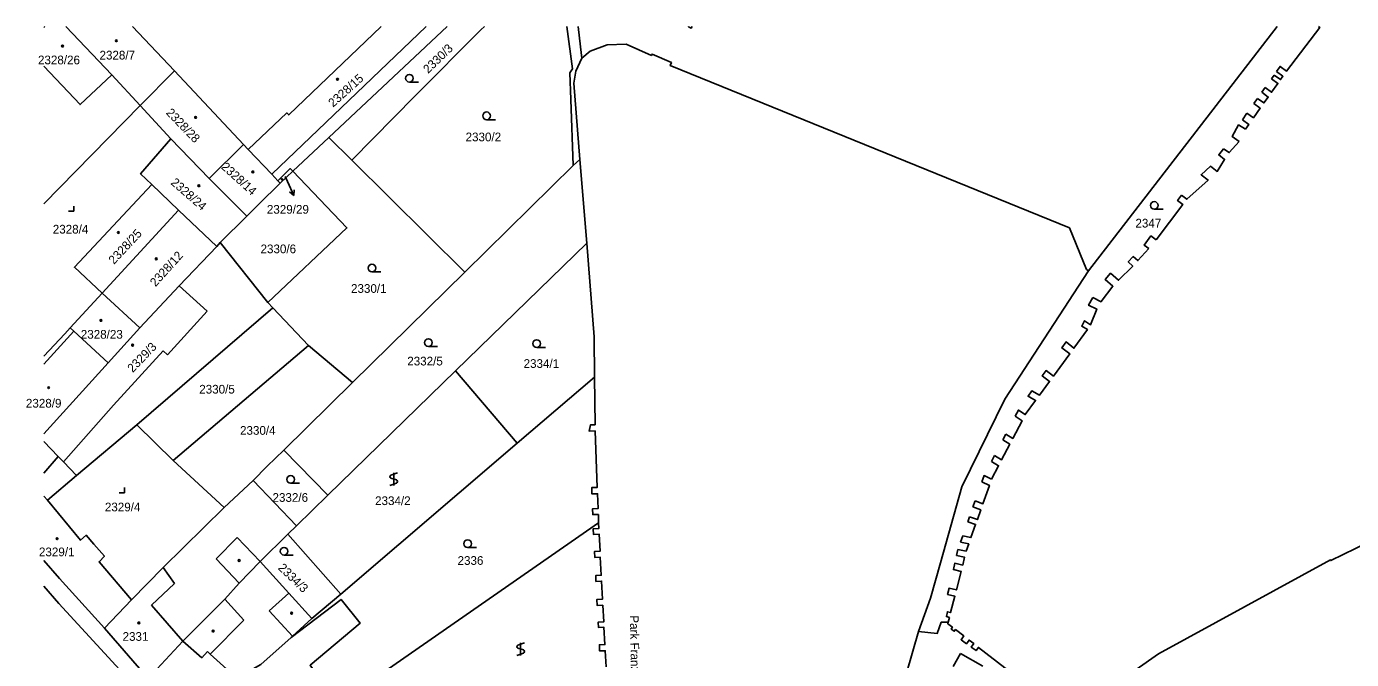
# Model space of a CAD drawing. Extents: x -600849 to -599899, y -1204328 to -1203436.
# Drawn here: x -600846.5 to -600587.3, y -1203561.9 to -1203438.2 of the extents above; entities that cross this region are included whole.
import ezdxf

# ---------------------------------------------------------------- set-up
doc = ezdxf.new("R2010")
doc.units = 0
for name, color, linetype in [('Vrstva 1', 7, 'Continuous'), ('Vrstva 2', 7, 'Continuous'), ('Vrstva 3', 7, 'Continuous'), ('Vrstva 4', 7, 'Continuous'), ('Vrstva 5', 7, 'Continuous'), ('Vrstva 7', 7, 'Continuous')]:
    doc.layers.add(name, color=color, linetype=linetype)

msp = doc.modelspace()

# ---------------------------------------------------------------- linework, layer by layer
at = {"layer": 'Vrstva 1'}
for p, q in [((-600843.16, -1203438.38), (-600842.94, -1203438.18)), ((-600838.82, -1203438.18), (-600829.8, -1203447.65)), ((-600825.76, -1203438.18), (-600817.54, -1203446.84)), ((-600787.39, -1203459.87), (-600764.25, -1203438.18)), ((-600756.95, -1203438.18), (-600757.64, -1203438.83)), ((-600738.62, -1203438.18), (-600738.16, -1203442.17)), ((-600638.77, -1203485.91), (-600601.89, -1203438.18)), ((-600738.16, -1203442.17), (-600737.91, -1203444.35)), ((-600737.91, -1203444.35), (-600739.05, -1203446.92)), ((-600829.8, -1203447.65), (-600824.28, -1203453.64)), ((-600824.28, -1203453.64), (-600817.54, -1203446.84)), ((-600817.54, -1203446.84), (-600804.07, -1203461.23)), ((-600739.05, -1203446.92), (-600739.48, -1203449.28)), ((-600602.47, -1203447.67), (-600602.99, -1203448.4)), ((-600739.48, -1203449.28), (-600738.28, -1203464.19)), ((-600604.21, -1203450.12), (-600604.85, -1203451.02)), ((-600605.72, -1203452.24), (-600606.44, -1203453.26)), ((-600818.26, -1203460.12), (-600824.28, -1203453.64)), ((-600607.78, -1203455.14), (-600608.68, -1203456.41)), ((-600810.81, -1203467.88), (-600818.26, -1203460.12)), ((-600794.44, -1203466.48), (-600787.39, -1203459.87)), ((-600782.9, -1203464.28), (-600787.39, -1203459.87)), ((-600804.07, -1203461.23), (-600810.81, -1203467.88)), ((-600804.07, -1203461.23), (-600803.13, -1203462.23)), ((-600798.54, -1203467.06), (-600803.13, -1203462.23)), ((-600760.8, -1203486.2), (-600782.9, -1203464.28)), ((-600760.8, -1203486.2), (-600739.59, -1203465.37)), ((-600739.59, -1203465.37), (-600738.28, -1203464.19)), ((-600738.28, -1203464.19), (-600736.94, -1203480.55)), ((-600803.43, -1203475.24), (-600810.81, -1203467.88)), ((-600798.54, -1203467.06), (-600797.34, -1203468.33)), ((-600797.34, -1203468.33), (-600796.88, -1203468.81)), ((-600796.88, -1203468.81), (-600794.44, -1203466.48)), ((-600822.02, -1203469.05), (-600816.81, -1203474.09)), ((-600816.81, -1203474.09), (-600831.7, -1203490.3)), ((-600816.81, -1203474.09), (-600809.32, -1203481.16)), ((-600808.61, -1203480.42), (-600803.43, -1203475.24)), ((-600809.32, -1203481.16), (-600808.61, -1203480.42)), ((-600799.3, -1203492.1), (-600808.61, -1203480.42)), ((-600736.94, -1203480.55), (-600762.57, -1203505.5)), ((-600782.77, -1203507.78), (-600760.8, -1203486.2)), ((-600638.77, -1203485.91), (-600639.18, -1203485.68)), ((-600837.97, -1203497.1), (-600831.7, -1203490.3)), ((-600831.7, -1203490.3), (-600824.36, -1203497.1)), ((-600798.33, -1203493.2), (-600799.3, -1203492.1)), ((-600824.93, -1203516.07), (-600798.33, -1203493.2)), ((-600798.33, -1203493.2), (-600791.38, -1203500.55)), ((-600824.36, -1203497.1), (-600830.56, -1203503.92)), ((-600791.38, -1203500.55), (-600817.85, -1203523.03)), ((-600791.38, -1203500.55), (-600782.77, -1203507.78)), ((-600843.16, -1203517.79), (-600830.56, -1203503.92)), ((-600762.57, -1203505.5), (-600787.55, -1203529.8)), ((-600762.57, -1203505.5), (-600750.51, -1203519.63)), ((-600750.51, -1203519.63), (-600735.41, -1203506.75)), ((-600796.21, -1203521.02), (-600782.77, -1203507.78)), ((-600836.71, -1203525.94), (-600824.93, -1203516.07)), ((-600817.85, -1203523.03), (-600824.93, -1203516.07)), ((-600654.94, -1203517.85), (-600655.54, -1203518.98)), ((-600785.06, -1203549.11), (-600750.51, -1203519.63)), ((-600807.86, -1203532.23), (-600817.85, -1203523.03)), ((-600796.21, -1203521.02), (-600787.55, -1203529.8)), ((-600657.15, -1203522.06), (-600657.75, -1203523.21)), ((-600807.86, -1203532.23), (-600802.2, -1203526.91)), ((-600793.69, -1203535.78), (-600802.2, -1203526.91)), ((-600787.55, -1203529.8), (-600793.69, -1203535.78)), ((-600660.94, -1203530.89), (-600661.37, -1203532.1)), ((-600795.37, -1203537.41), (-600793.69, -1203535.78)), ((-600775.68, -1203563.75), (-600734.6, -1203535.17)), ((-600662.05, -1203534.02), (-600662.39, -1203534.97)), ((-600800.83, -1203542.73), (-600795.37, -1203537.41)), ((-600795.37, -1203537.41), (-600785.06, -1203549.11)), ((-600663.38, -1203537.75), (-600663.81, -1203538.96)), ((-600662.69, -1203540.71), (-600664.31, -1203540.38)), ((-600790.69, -1203553.92), (-600785.06, -1203549.11)), ((-600831.29, -1203555.77), (-600825.96, -1203550.26)), ((-600831.29, -1203555.77), (-600822.7, -1203565.64))]:
    msp.add_line(p, q, dxfattribs=at)
for points in [[(-600803.13, -1203462.23), (-600795.62, -1203455.06), (-600795.23, -1203455.47), (-600777.13, -1203438.18)], [(-600768.31, -1203438.18), (-600798.54, -1203467.06)], [(-600757.64, -1203438.83), (-600770.46, -1203451.74), (-600782.9, -1203464.28)], [(-600739.59, -1203465.37), (-600740.02, -1203452.46), (-600740.25, -1203447.21), (-600739.73, -1203446.47), (-600740.82, -1203438.18)], [(-600716.33, -1203438.18), (-600716.5, -1203438.5), (-600717.01, -1203438.22), (-600716.99, -1203438.18)], [(-600593.79, -1203438.18), (-600593.5, -1203438.4), (-600600.05, -1203446.92), (-600601.28, -1203445.99), (-600601.99, -1203446.99)], [(-600639.18, -1203485.68), (-600642.5, -1203477.51), (-600720.6, -1203445.83), (-600720.35, -1203445.24), (-600724.15, -1203443.57), (-600724.28, -1203443.82), (-600729.2, -1203441.64), (-600732.9, -1203441.76), (-600736.24, -1203443.02), (-600737.91, -1203444.35)], [(-600843.16, -1203445.94), (-600836.05, -1203453.45), (-600829.8, -1203447.65)], [(-600601.99, -1203446.99), (-600600.74, -1203447.9), (-600601.21, -1203448.56), (-600602.47, -1203447.67)], [(-600602.99, -1203448.4), (-600601.73, -1203449.3), (-600602.95, -1203451.02), (-600604.21, -1203450.12)], [(-600604.85, -1203451.02), (-600603.62, -1203451.96), (-600604.45, -1203453.13), (-600605.72, -1203452.24)], [(-600824.28, -1203453.64), (-600843.16, -1203472.86)], [(-600606.44, -1203453.26), (-600605.18, -1203454.16), (-600606.51, -1203456.03), (-600607.78, -1203455.14)], [(-600608.09, -1203458.26), (-600609.4, -1203457.43), (-600610.7, -1203459.66), (-600609.28, -1203460.68)], [(-600608.68, -1203456.41), (-600607.42, -1203457.32), (-600608.09, -1203458.26)], [(-600822.02, -1203469.05), (-600824.19, -1203466.95), (-600818.26, -1203460.12)], [(-600609.28, -1203460.68), (-600611.25, -1203462.82), (-600612.35, -1203462.1)], [(-600612.35, -1203462.1), (-600613.31, -1203463.28), (-600612.15, -1203464.15), (-600613.6, -1203466.5), (-600614.92, -1203465.5), (-600616.74, -1203467.17), (-600615.39, -1203468.2), (-600619.53, -1203471.96), (-600620.57, -1203471.17)], [(-600797.34, -1203468.33), (-600794.95, -1203465.94), (-600794.44, -1203466.48)], [(-600794.44, -1203466.48), (-600783.85, -1203477.55), (-600799.3, -1203492.1)], [(-600831.7, -1203490.3), (-600837.16, -1203485.24), (-600822.02, -1203469.05)], [(-600796.88, -1203468.81), (-600801.08, -1203472.89), (-600803.43, -1203475.24)], [(-600620.57, -1203471.17), (-600621.35, -1203472.2), (-600620.31, -1203472.99), (-600625.51, -1203479.89)], [(-600625.51, -1203479.89), (-600626.55, -1203479.11), (-600627.89, -1203480.89), (-600626.97, -1203481.58)], [(-600809.32, -1203481.16), (-600816.68, -1203488.88), (-600824.36, -1203497.1)], [(-600735.41, -1203506.75), (-600735.5, -1203498.84), (-600736.94, -1203480.55)], [(-600626.97, -1203481.58), (-600629.1, -1203483.94), (-600630.02, -1203483.14), (-600631, -1203484.17), (-600630.11, -1203485.01), (-600632.88, -1203487.78), (-600634.44, -1203486.41), (-600635.54, -1203487.63), (-600634, -1203488.94), (-600636.27, -1203491.93), (-600636.32, -1203492.02), (-600637.91, -1203491.16)], [(-600645.19, -1203571.16), (-600643.45, -1203572.4), (-600642.87, -1203572.55), (-600642.3, -1203572.31), (-600640.94, -1203570.26), (-600640.09, -1203571.18), (-600633.19, -1203566.46), (-600625.08, -1203560.78), (-600591.46, -1203542.4), (-600591.38, -1203542.56), (-600581.75, -1203537.86), (-600573.23, -1203533.09), (-600569.96, -1203531.02), (-600565.64, -1203527.34), (-600560.36, -1203521.05), (-600553.06, -1203512.74), (-600552.4, -1203511.74), (-600551.87, -1203510.65), (-600546.9, -1203499.62), (-600543.15, -1203494.15), (-600536.39, -1203488.52), (-600530.27, -1203484.25)], [(-600672.01, -1203556.42), (-600669.7, -1203549.89), (-600667.72, -1203543.01), (-600663.57, -1203528.16), (-600655.12, -1203511.05), (-600638.77, -1203485.91)], [(-600637.91, -1203491.16), (-600638.75, -1203492.65), (-600637.17, -1203493.42), (-600638.35, -1203496.49), (-600639.54, -1203495.69), (-600640.1, -1203496.76), (-600638.97, -1203497.43), (-600641.64, -1203501.07), (-600643.16, -1203499.83), (-600643.97, -1203500.99), (-600642.44, -1203502.16), (-600645.64, -1203506.51), (-600647.07, -1203505.42), (-600647.82, -1203506.49), (-600646.4, -1203507.56), (-600648.35, -1203510.21), (-600649.86, -1203509.4), (-600650.59, -1203510.45), (-600649.12, -1203511.26), (-600651.15, -1203514.03), (-600652.48, -1203513.15), (-600653.1, -1203514.34)], [(-600843.16, -1203502.61), (-600839.03, -1203498.26), (-600837.97, -1203497.1)], [(-600830.56, -1203503.92), (-600837.26, -1203497.75), (-600837.97, -1203497.1)], [(-600734.6, -1203535.17), (-600734.66, -1203533.57), (-600735.75, -1203533.59), (-600735.79, -1203532.45), (-600734.7, -1203532.42), (-600734.81, -1203529.5), (-600735.9, -1203529.53), (-600735.95, -1203528.3), (-600734.86, -1203528.27), (-600735.28, -1203517.23), (-600736.48, -1203517.25), (-600736.19, -1203516.03), (-600735.29, -1203516.01), (-600735.41, -1203506.75)], [(-600653.1, -1203514.34), (-600651.78, -1203515.23), (-600653.59, -1203518.7), (-600654.94, -1203517.85)], [(-600836.71, -1203525.94), (-600839.3, -1203523.28), (-600840.34, -1203522.21), (-600843.16, -1203519.3)], [(-600655.54, -1203518.98), (-600654.18, -1203519.84), (-600655.77, -1203522.88), (-600657.15, -1203522.06)], [(-600802.2, -1203526.91), (-600799.46, -1203524.15), (-600796.21, -1203521.02)], [(-600657.75, -1203523.21), (-600656.37, -1203524.03), (-600657.74, -1203526.66)], [(-600825.96, -1203550.26), (-600832.33, -1203542.79), (-600831.27, -1203541.72), (-600833.33, -1203539.37), (-600834.83, -1203537.61), (-600835.93, -1203538.59), (-600842.44, -1203530.74), (-600836.71, -1203525.94)], [(-600659.63, -1203527.2), (-600658.17, -1203527.87), (-600659.44, -1203531.47), (-600660.94, -1203530.89)], [(-600657.74, -1203526.66), (-600659.19, -1203525.96), (-600659.63, -1203527.2)], [(-600825.96, -1203550.26), (-600819.82, -1203543.91), (-600807.86, -1203532.23)], [(-600661.37, -1203532.1), (-600659.86, -1203532.67), (-600660.52, -1203534.56), (-600662.05, -1203534.02)], [(-600733.15, -1203563.35), (-600733.32, -1203560.2), (-600734.4, -1203560.24), (-600734.46, -1203559.04), (-600733.38, -1203558.98), (-600733.56, -1203555.62), (-600734.65, -1203555.65), (-600734.71, -1203554.62), (-600733.6, -1203554.56), (-600733.78, -1203551.32), (-600734.87, -1203551.38), (-600734.94, -1203550.15), (-600733.84, -1203550.1), (-600734.03, -1203546.59), (-600735.12, -1203546.66), (-600735.18, -1203545.49), (-600734.08, -1203545.43), (-600734.28, -1203541.92), (-600735.37, -1203541.94), (-600735.42, -1203540.8), (-600734.31, -1203540.74), (-600734.47, -1203537.43), (-600735.6, -1203537.49), (-600735.66, -1203536.35), (-600734.56, -1203536.28), (-600734.6, -1203535.17)], [(-600662.39, -1203534.97), (-600660.85, -1203535.5), (-600661.77, -1203538.09), (-600663.38, -1203537.75)], [(-600664.31, -1203540.38), (-600664.58, -1203541.58), (-600663, -1203541.93), (-600663.38, -1203543.44), (-600664.93, -1203543.09), (-600665.21, -1203544.33), (-600663.7, -1203544.7), (-600664.61, -1203548.3), (-600666.05, -1203547.98), (-600666.33, -1203549.23), (-600664.92, -1203549.54), (-600665.74, -1203552.75), (-600666.36, -1203552.59), (-600666.58, -1203553.53), (-600665.97, -1203553.67), (-600666.21, -1203554.6)], [(-600663.81, -1203538.96), (-600662.2, -1203539.31), (-600662.69, -1203540.71)], [(-600843.16, -1203542.53), (-600840.04, -1203546.05), (-600831.29, -1203555.77)], [(-600822.7, -1203565.64), (-600815.96, -1203558.31), (-600807.75, -1203550.12), (-600804.94, -1203546.96), (-600800.83, -1203542.73)], [(-600790.69, -1203553.92), (-600795.22, -1203548.93), (-600800.83, -1203542.73)], [(-600843.16, -1203547.59), (-600840.17, -1203550.97), (-600827.54, -1203564.68), (-600820.22, -1203571.95), (-600772.49, -1203617.73), (-600738.37, -1203650.36), (-600721.29, -1203666.47), (-600702.75, -1203684.47), (-600689.43, -1203700.21), (-600686.84, -1203705.75), (-600685.14, -1203709.49), (-600678.92, -1203716.93), (-600670.04, -1203723.78), (-600660.52, -1203728.8)], [(-600785.6, -1203571.09), (-600790.43, -1203563.85), (-600791.05, -1203563.04), (-600781.27, -1203554.83), (-600784.97, -1203550.17), (-600794.75, -1203557.61)], [(-600794.75, -1203557.61), (-600794.49, -1203557.37), (-600790.69, -1203553.92)], [(-600683.89, -1203589.16), (-600680.28, -1203585.19), (-600672.01, -1203556.42)], [(-600666.21, -1203554.6), (-600667.57, -1203554.64), (-600668.36, -1203556.82), (-600672.01, -1203556.42)], [(-600646.29, -1203570.38), (-600660.31, -1203559.54), (-600660.78, -1203560.18), (-600661.71, -1203559.49), (-600661.23, -1203558.81), (-600662.13, -1203558.13), (-600662.64, -1203558.82), (-600663.7, -1203558.04), (-600663.18, -1203557.31), (-600664.79, -1203556.07), (-600665.02, -1203556.38), (-600665.63, -1203555.95), (-600665.4, -1203555.59), (-600666.29, -1203554.91), (-600666.21, -1203554.6)], [(-600813.37, -1203575.24), (-600805.37, -1203565.58), (-600800.69, -1203562.91), (-600794.75, -1203557.61)]]:
    msp.add_lwpolyline(points, dxfattribs=at)
at = {"layer": 'Vrstva 3'}
for p, q in [((-600771.61, -1203449.05), (-600769.86, -1203449.05)), ((-600756.53, -1203456.39), (-600754.78, -1203456.39)), ((-600837.28, -1203474.28), (-600837.28, -1203473.28)), ((-600625.91, -1203473.91), (-600624.16, -1203473.91)), ((-600838.28, -1203474.28), (-600837.28, -1203474.28)), ((-600778.94, -1203486.15), (-600777.19, -1203486.15)), ((-600767.9, -1203500.72), (-600766.15, -1203500.72)), ((-600746.72, -1203500.9), (-600744.97, -1203500.9)), ((-600773.93, -1203525.4), (-600775.23, -1203525.88)), ((-600774.68, -1203525.4), (-600774.68, -1203527.9)), ((-600827.37, -1203529.32), (-600827.37, -1203528.32)), ((-600794.85, -1203527.46), (-600793.1, -1203527.46)), ((-600775.43, -1203527.9), (-600774.13, -1203527.41)), ((-600775.23, -1203526.48), (-600774.13, -1203526.81)), ((-600828.37, -1203529.32), (-600827.37, -1203529.32)), ((-600760.22, -1203540.02), (-600758.47, -1203540.02)), ((-600796.13, -1203541.5), (-600794.38, -1203541.5)), ((-600749.11, -1203558.63), (-600750.41, -1203559.11)), ((-600749.86, -1203558.63), (-600749.86, -1203561.13)), ((-600750.61, -1203561.13), (-600749.31, -1203560.64)), ((-600750.41, -1203559.71), (-600749.31, -1203560.04))]:
    msp.add_line(p, q, dxfattribs=at)
for centre in [(-600771.61, -1203448.3), (-600756.53, -1203455.64), (-600625.91, -1203473.16), (-600778.94, -1203485.4), (-600767.9, -1203499.97), (-600746.72, -1203500.15), (-600794.85, -1203526.71), (-600760.22, -1203539.27), (-600796.13, -1203540.75)]:
    msp.add_circle(centre, 0.75, dxfattribs=at)
for centre, start, end in [((-600775.1, -1203526.18), 113.579, 246.421), ((-600774.26, -1203527.11), 293.574, 66.426), ((-600750.28, -1203559.41), 113.579, 246.421), ((-600749.44, -1203560.34), 293.574, 66.426)]:
    msp.add_arc(centre, 0.329, start, end, dxfattribs=at)
at = {"layer": 'Vrstva 4'}
for p, q in [((-600816.68, -1203488.88), (-600811.2, -1203493.81)), ((-600818.91, -1203502.38), (-600811.2, -1203493.81)), ((-600843.16, -1203504.18), (-600837.26, -1203497.75)), ((-600829.5, -1203512.17), (-600819.78, -1203501.6)), ((-600819.78, -1203501.6), (-600818.91, -1203502.38)), ((-600839.3, -1203523.28), (-600829.5, -1203512.17)), ((-600843.16, -1203525.48), (-600840.34, -1203522.21)), ((-600843.16, -1203529.97), (-600842.44, -1203530.74)), ((-600805.3, -1203538.03), (-600809.39, -1203542.2)), ((-600800.83, -1203542.73), (-600805.3, -1203538.03)), ((-600817.59, -1203547.04), (-600819.82, -1203543.91)), ((-600809.39, -1203542.2), (-600804.94, -1203546.96)), ((-600822.05, -1203551.32), (-600817.59, -1203547.04)), ((-600799.02, -1203552.38), (-600795.22, -1203548.93)), ((-600815.96, -1203558.31), (-600822.05, -1203551.32)), ((-600804.02, -1203554.25), (-600807.75, -1203550.12)), ((-600810.57, -1203560.89), (-600804.02, -1203554.25)), ((-600794.49, -1203557.37), (-600799.02, -1203552.38)), ((-600815.96, -1203558.31), (-600812.23, -1203561.58)), ((-600812.23, -1203561.58), (-600811.14, -1203560.34)), ((-600811.14, -1203560.34), (-600810.57, -1203560.89)), ((-600810.57, -1203560.89), (-600805.37, -1203565.58)), ((-600665.22, -1203563.27), (-600663.81, -1203560.74)), ((-600663.81, -1203560.74), (-600659.45, -1203563.22))]:
    msp.add_line(p, q, dxfattribs=at)
at = {"layer": 'Vrstva 5'}
for centre, radius in [((-600839.47, -1203442.01), 0.175), ((-600828.95, -1203440.96), 0.175), ((-600785.69, -1203448.49), 0.175), ((-600813.44, -1203455.95), 0.175), ((-600802.24, -1203466.61), 0.175), ((-600796.55, -1203468.05), 0.117), ((-600812.8, -1203469.31), 0.175), ((-600828.56, -1203478.44), 0.175), ((-600821.14, -1203483.59), 0.175), ((-600831.96, -1203495.63), 0.175), ((-600825.77, -1203500.46), 0.175), ((-600842.19, -1203508.78), 0.175), ((-600840.54, -1203538.29), 0.175), ((-600804.93, -1203542.55), 0.175), ((-600794.66, -1203552.85), 0.175), ((-600824.54, -1203554.76), 0.175), ((-600810.01, -1203556.35), 0.175)]:
    msp.add_circle(centre, radius, dxfattribs=at)
at = {"layer": 'Vrstva 7'}
for p, q in [((-600795.93, -1203467.52), (-600795.49, -1203468.48)), ((-600795.49, -1203468.48), (-600794.22, -1203471.2)), ((-600794.22, -1203471.2), (-600795.1, -1203470.5)), ((-600794.22, -1203471.2), (-600794.19, -1203470.08))]:
    msp.add_line(p, q, dxfattribs=at)

# ---------------------------------------------------------------- texts
at = {"layer": 'Vrstva 2'}
for s, p in [('2328/7', (-600832.24, -1203444.63)), ('2328/26', (-600844.28, -1203445.57)), ('2330/2', (-600760.63, -1203460.62)), ('2329/29', (-600799.5, -1203474.77)), ('2347', (-600629.59, -1203477.47)), ('2328/4', (-600841.38, -1203478.65)), ('2330/6', (-600800.74, -1203482.5)), ('2330/1', (-600783.04, -1203490.24)), ('2328/23', (-600835.9, -1203499.2)), ('2332/5', (-600772.04, -1203504.43)), ('2334/1', (-600749.28, -1203504.91)), ('2330/5', (-600812.73, -1203509.93)), ('2328/9', (-600846.64, -1203512.67)), ('2330/4', (-600804.75, -1203517.98)), ('2332/6', (-600798.4, -1203531.09)), ('2334/2', (-600778.33, -1203531.72)), ('2329/4', (-600831.19, -1203532.95)), ('2329/1', (-600844.09, -1203541.73)), ('2336', (-600762.2, -1203543.41)), ('2331', (-600827.73, -1203558.26))]:
    msp.add_text(s, height=1.7, dxfattribs=at).set_placement(p)
for s, rotation, p in [('2330/3', 44, (-600767.95, -1203447.47)), ('2328/15', 42, (-600786.55, -1203454.05)), ('2328/28', 314, (-600819.35, -1203455.15)), ('2328/14', 318, (-600808.56, -1203465.81)), ('2328/24', 319, (-600818.44, -1203468.89)), ('2328/25', 47, (-600829.41, -1203484.78)), ('2328/12', 48, (-600821.28, -1203489.16)), ('2329/3', 46, (-600825.75, -1203505.93)), ('2334/3', 316, (-600797.42, -1203544.15))]:
    msp.add_text(s, height=1.7, rotation=rotation, dxfattribs=at).set_placement(p)
at = {"layer": 'Vrstva 7'}
msp.add_text('Park Franze von Sonnenfelse', height=1.7, rotation=271, dxfattribs=at).set_placement((-600728.48, -1203553.3))

doc.saveas('drawing.dxf')
